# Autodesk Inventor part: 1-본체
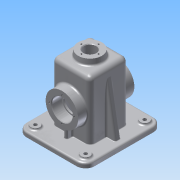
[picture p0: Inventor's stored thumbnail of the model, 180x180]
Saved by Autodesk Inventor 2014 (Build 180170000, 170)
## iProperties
Created: 2015-12
Part Number: 1-본체
Material: 알루미늄 6061
Document SubType Name: Modeling
Designer: Administrator
Density: 2.71 g/cm^3
Appearance: 알루미늄 - 평지
Mass: 806.27 g
Surface Area: 909.583 cm^2
Volume: 297.517 cm^3
Author: Administrator
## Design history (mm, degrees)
sketch "스케치1"
  geometry: L1 (-32.5, 32.5)-(32.5, 32.5); L2 (32.5, 32.5)-(32.5, -32.5); L3 (32.5, -32.5)-(-32.5, -32.5); L4 (-32.5, -32.5)-(-32.5, 32.5); L5 (-32.5, 32.5)-(32.5, -32.5); L6 (32.5, 32.5)-(-32.5, -32.5); 1 further point
  constraints: 12 end point, 2 midpoint, 2 parallel, 1 horizontal, 1 perpendicular
  dimensions: "d0" = 65 distance of L2.end L3.end; "d1" = 65 distance of L1.end L2.end
extrude "돌출1" new body sketch "스케치1" distance "d2" = 55; taper "d4" = 0 deg; dims "d3" = 55, "d5" = 0
feature "쉘1" dims "d6" = 5
node "작업 평면1"
sketch "스케치2"
  geometry: C1 r 20 at (0, 0); 1 further point
  constraints: 1 centre point, 1 coincident
  dimensions: "d8" = 40 diameter of C1
extrude "돌출2" join sketch "스케치2" stored distance "d9" = 55; taper "d10" = 5 deg
sketch "스케치3"
  geometry: C1 r 20 at (0, 0) reference; C2 r 10.5 at (0, 0)
  constraints: 1 centre point, 1 coincident
  dimensions: "d11" = 21 diameter of C2
extrude "돌출3" cut sketch "스케치3" stored distance "d12" = 55; taper "d13" = 0 deg
sketch "스케치4" dims "d14" = 29
  geometry: C1 r 20 at (0, 0) reference; 2 further points
  constraints: 1 coincident, 1 vertical alignment, 2 other
hole "구멍1" sketch "스케치4" at (0, 14.5) diameter "d15" = 2.459; stored, may be unused: countersink angle "d19" = 90 deg, drill point angle "d21" = 118 deg; dims "d16" = 7, "d17" = 4, "d18" = 2, "d20" = 9
sketch "스케치5"
  geometry: C1 r 27.5 at (32.5, -55); 1 further point
  constraints: 1 centre point, 1 coincident
  dimensions: "d25" = 55 diameter of C1
extrude "돌출4" join sketch "스케치5" distance "d26" = 15; taper "d27" = 0 deg
sketch "스케치6"
  geometry: C1 r 27.5 at (0, 0) reference; C2 r 17.5 at (0, 0)
  constraints: 1 centre point, 1 coincident
  dimensions: "d28" = 35 diameter of C2
extrude "돌출5" cut sketch "스케치6" distance "d29" = 17; taper "d30" = 0 deg
sketch "스케치7"
  geometry: C1 r 17.5 at (0, 0) reference; C2 r 15 at (0, 0)
  constraints: 1 centre point, 1 coincident
  dimensions: "d31" = 30 diameter of C2
extrude "돌출6" cut sketch "스케치7" distance "d32" = 3; taper "d33" = 0 deg
sketch "스케치8" dims "d34" = 42
  geometry: C1 r 27.5 at (0, 0) reference; 2 further points
  constraints: 1 coincident, 1 vertical alignment, 2 other
hole "구멍2" sketch "스케치8" at (0, 21) diameter "d35" = 3.242; stored, may be unused: countersink angle "d39" = 90 deg, drill point angle "d41" = 118 deg; dims "d36" = 8, "d37" = 4, "d38" = 2, "d40" = 10
sketch "스케치9"
  geometry: L1 (32.5, 32.5)-(-32.5, 32.5) reference; L2 (-32.5, 32.5)-(-32.5, -32.5) reference; L3 (-32.5, -32.5)-(32.5, -32.5) reference; L4 (32.5, -32.5)-(32.5, 32.5) reference; L5 (-42.5, -60)-(42.5, -60); L6 (52.5, -50)-(52.5, 50); L7 (42.5, 60)-(-42.5, 60); L8 (-52.5, 50)-(-52.5, -50); L9 (-52.5, -60)-(52.5, 60); L10 (52.5, -60)-(-52.5, 60); A1 r 10 centre (-42.5, -50) between (-52.5, -50) and (-42.5, -60); A2 r 10 centre (42.5, -50) between (42.5, -60) and (52.5, -50); A3 r 10 centre (42.5, 50) between (52.5, 50) and (42.5, 60); A4 r 10 centre (-42.5, 50) between (-42.5, 60) and (-52.5, 50); 1 further point
  constraints: 12 end point, 8 point on circle, 8 point on line, 8 tangent, 4 centre point, 3 equal radius, 2 midpoint, 2 parallel, 1 horizontal, 1 perpendicular
  dimensions: "d45" = 105 distance of L10.end L9.end; "d46" = 120 distance of L9.end L10.start; "d47" = 10 radius of A1
extrude "돌출7" join sketch "스케치9" distance "d48" = 2; taper "d49" = 0 deg
sketch "스케치10"
  geometry: L1 (32.5, -32.5)-(32.5, 32.5) reference; L2 (-32.5, -32.5)-(32.5, -32.5) reference; L3 (-32.5, 32.5)-(-32.5, -32.5) reference; L4 (32.5, 32.5)-(-32.5, 32.5) reference; L5 (42.5, -65)-(-42.5, -65); L6 (-57.5, -50)-(-57.5, 50); L7 (-42.5, 65)-(42.5, 65); L8 (57.5, 50)-(57.5, -50); L9 (57.5, -65)-(-57.5, 65); L10 (-57.5, -65)-(57.5, 65); A1 r 15 centre (42.5, -50) between (42.5, -65) and (57.5, -50); A2 r 15 centre (-42.5, -50) between (-57.5, -50) and (-42.5, -65); A3 r 15 centre (-42.5, 50) between (-42.5, 65) and (-57.5, 50); A4 r 15 centre (42.5, 50) between (57.5, 50) and (42.5, 65); 1 further point
  constraints: 12 end point, 8 point on circle, 8 point on line, 8 tangent, 4 centre point, 2 midpoint, 2 parallel, 1 horizontal, 1 perpendicular
  dimensions: "d50" = 115 distance of L9.end L10.end; "d51" = 130 distance of L10.start L9.end; "d52" = 15 radius of A1; "d53" = 15 radius of A2; "d54" = 15 radius of A3; "d55" = 15 radius of A4
extrude "돌출8" join sketch "스케치10" distance "d56" = 8; taper "d57" = 0 deg
sketch "스케치11"
  geometry: C1 r 3 at (-42.5, -50); C2 r 3 at (-42.5, 50); C3 r 3 at (42.5, 50); C4 r 3 at (42.5, -50); A1 r 10 centre (42.5, -50) between (42.5, -60) and (52.5, -50) reference; A2 r 10 centre (42.5, 50) between (52.5, 50) and (42.5, 60) reference; A3 r 10 centre (-42.5, 50) between (-42.5, 60) and (-52.5, 50) reference; A4 r 10 centre (-42.5, -50) between (-52.5, -50) and (-42.5, -60) reference; 1 further point
  constraints: 4 centre point, 4 coincident
  dimensions: "d58" = 6 diameter of C1; "d59" = 6 diameter of C2; "d60" = 6 diameter of C3; "d61" = 6 diameter of C4
extrude "돌출9" cut sketch "스케치11" distance "d62" = 10; taper "d63" = 0 deg
sketch "스케치12"
  geometry: C1 r 3 at (-42.5, 50) reference; C2 r 3 at (42.5, -50) reference; C3 r 3 at (42.5, 50) reference; C4 r 3 at (-42.5, -50) reference; C5 r 7.5 at (-42.5, -50); C6 r 7.5 at (-42.5, 50); C7 r 7.5 at (42.5, 50); C8 r 7.5 at (42.5, -50); A1 r 15 centre (42.5, -50) between (42.5, -65) and (57.5, -50) reference; A2 r 15 centre (42.5, 50) between (57.5, 50) and (42.5, 65) reference; A3 r 15 centre (-42.5, 50) between (-42.5, 65) and (-57.5, 50) reference; A4 r 15 centre (-42.5, -50) between (-57.5, -50) and (-42.5, -65) reference; 1 further point
  constraints: 4 centre point, 3 concentric, 1 coincident
  dimensions: "d64" = 15 diameter of C5; "d65" = 15 diameter of C6; "d66" = 15 diameter of C7; "d67" = 15 diameter of C8
extrude "돌출10" join sketch "스케치12" distance "d68" = 3; taper "d69" = 0 deg
sketch "스케치14"
  geometry: L1 (-27.5, 50)-(-27.5, -55) reference; L2 (-27.5, -55)-(-52.5, -55) reference; L3 (-52.5, -55)-(-52.5, -53) reference; L4 (-52.5, -53)-(-57.5, -53) reference; L5 (-57.5, -53)-(-57.5, -45) reference; L6 (-57.5, -45)-(-32.5, -45) reference; L7 (-32.5, -45)-(-32.5, 55) reference; L8 (-32.5, 55)-(-20.875, 55) reference; L9 (-20.875, 55)-(-20, 65) reference; L10 (-20, 65)-(-15.73, 65) reference; L11 (-15.73, 65)-(-15.73, 56) reference; L12 (-15.73, 56)-(-14.5, 55.261) reference; L13 (-14.5, 55.261)-(-13.27, 56) reference; L14 (-13.27, 56)-(-13.27, 65) reference; L15 (-13.27, 65)-(-10.5, 65) reference; L16 (-10.5, 65)-(-10.5, 50) reference; L17 (-10.5, 50)-(-27.5, 50) reference; L18 (27.5, -55)-(27.5, 50) reference; L19 (27.5, 50)-(10.5, 50) reference; L20 (10.5, 50)-(10.5, 65) reference; L21 (10.5, 65)-(13.27, 65) reference; L22 (13.27, 65)-(13.27, 56) reference; L23 (13.27, 56)-(14.5, 55.261) reference; L24 (14.5, 55.261)-(15.73, 56) reference; L25 (15.73, 56)-(15.73, 65) reference; L26 (15.73, 65)-(20, 65) reference; L27 (20, 65)-(20.875, 55) reference; L28 (20.875, 55)-(32.5, 55) reference; L29 (32.5, 55)-(32.5, -45) reference; L30 (32.5, -45)-(57.5, -45) reference; L31 (57.5, -45)-(57.5, -53) reference; L32 (57.5, -53)-(52.5, -53) reference; L33 (52.5, -53)-(52.5, -55) reference; L34 (52.5, -55)-(27.5, -55) reference; L35 (47.5, -45)-(32.5, 40.069); L36 (47.5, -45)-(147.172, -45); 1 further point
  constraints: 4 end point, 2 point on line, 1 horizontal
  dimensions: "d70" = 100 deg angle of L36 L35; "d71" = 10 distance of L30.end L35.start
feature "리브1" sketch "스케치14" dims "d72" = 1, "d73" = 10, "d74" = 0, "d75" = 0, "d76" = 1, "d77" = 1
sketch "스케치15"
  geometry: L1 (42.5, -45)-(42.5, -27.5); L2 (50, -55)-(-50, -55) reference; L3 (47.5, -27.5)-(32.5, -27.5) reference; L4 (-50, -45)-(50, -45) reference; L5 (27.5, 50)-(27.5, -55) reference; 1 further point
  constraints: 2 end point, 2 point on line
  dimensions: "d79" = 15 distance between parallel lines of L5 L1
feature "리브2" sketch "스케치15" dims "d80" = 1, "d81" = 6, "d82" = 0, "d83" = 0, "d84" = 1, "d85" = 1
sketch "스케치16"
  geometry: L1 (65, 0)-(65, 100) reference; L2 (52.5, -10)-(12.5, -10) reference; 1 further point
  constraints: 1 other
  dimensions: "d86" = 26 distance from line of point (32.5, 16) L2; "d87" = 32.5 distance from line of L1 point (32.5, 16)
feature "엠보싱1" sketch "스케치16" dims "d88" = 0.5, "d89" = 0
chamfer "모따기1" distance "d90" = 1; stored, may be unused: second distance "d91" = 2, angle "d92" = 45 deg
fillet "모깎기1" dims "d93" = 0.3
fillet "모깎기2" dims "d94" = 8
fillet "모깎기3" dims "d95" = 8
fillet "모깎기4" dims "d96" = 3
fillet "모깎기5" dims "d97" = 3
fillet "모깎기7" dims "d99" = 3
fillet "모깎기8" dims "d100" = 3
fillet "모깎기9" dims "d101" = 3
fillet "모깎기10" dims "d102" = 3
fillet "모깎기11" dims "d103" = 3
fillet "모깎기12" dims "d104" = 1
node "솔리드1"
pattern_circular "원형 패턴1" dims angle "d23" = 360 deg
pattern_circular "원형 패턴2" dims angle "d43" = 360 deg
mirror "대칭1"
mirror "대칭2"
mirror "대칭3"
node "절단 모서리 투영1"
other parameters: "d7" = 65
